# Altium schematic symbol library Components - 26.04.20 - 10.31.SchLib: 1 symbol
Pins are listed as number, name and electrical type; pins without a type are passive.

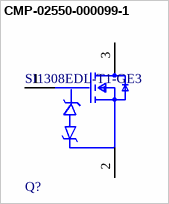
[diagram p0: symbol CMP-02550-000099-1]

## CMP-02550-000099-1
designator Q?, comment SI1308EDL-T1-GE3
MOSFET N-CH 30V 1.4A SC-70-3; Manufacturer: Vishay; Threshold Vgs Max: 1.5V; Turn On Delay Time: 2ns; Gate Charge At Vgs: 2.7nC @ 10V; Typ Forward Diode Voltage: 0.8V; Gate To Source Voltage: 12V; Max Junction Temp: +150°C; Pulse Drain Current: 6A; Threshold Vgs Min: 0.6V; Number Of Channels: 1; Transconductance: 5S; Continuous Drain Current: 1.5A; Rthja Max: 250°C/W; Turn Off Delay Time: 8ns; Power Dissipation: 0.4W; Input Capacitace At Vds: 105pF @ 15V; Max Forward Diode Voltage: 1.2V; Reverse Recovery Charge: 3nC; Depletion Mode: False; Drain To Source Resistance: 0.11Ω
footprint FP-S-03946-IPC_A
footprint FP-S-03946-IPC_C
footprint FP-S-03946-MFG
footprint FP-S-03946-IPC_B
pins: 1 G, 2 S, 3 D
